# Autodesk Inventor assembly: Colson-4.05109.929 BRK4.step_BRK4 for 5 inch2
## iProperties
Created: 2010-10
Part Number: Colson-4.05109.929 BRK4.step_BRK4 for 5 inch2
Document SubType Name: Assembly
Designer: Administrator
Author: Administrator
